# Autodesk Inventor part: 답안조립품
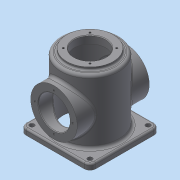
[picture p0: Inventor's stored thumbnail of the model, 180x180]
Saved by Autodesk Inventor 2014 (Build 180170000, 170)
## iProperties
Created: 2015-10
Part Number: 답안조립품
Material: 일반
Document SubType Name: Modeling
Designer: net
Density: 1 g/cm^3
Appearance: 기본값
Author: net
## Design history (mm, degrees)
sketch "스케치1"
  geometry: L1 (60, -60)-(-60, -60); L2 (-60, -60)-(-60, 60); L3 (-60, 60)-(60, 60); L4 (60, 60)-(60, -60); L5 (60, 0)-(-60, 0); C1 r 4 at (50, -50); C2 r 4 at (-50, -50); C3 r 4 at (50, 50); C4 r 4 at (-50, 50); 2 further points
  constraints: 10 end point, 4 centre point, 3 midpoint, 2 horizontal alignment, 2 parallel, 2 perpendicular, 2 symmetric about line, 1 equal radius, 1 horizontal, 1 vertical alignment, 2 other
  dimensions: "d0" = 120 distance of L1.start L1.end; "d1" = 120 distance of L1.end L2.end; "d2" = 8 diameter of C1; "d3" = 50 horizontal distance of C1.centre point (0, 0); "d4" = 50 horizontal distance of point (0, 0) C1.centre; "d5" = 100 distance of C2.centre C1.centre
extrude "돌출1" new body sketch "스케치1" distance "d6" = 10; taper "d7" = 0 deg
fillet "모깎기1" dims "d8" = 10
node "작업 평면2"
sketch "스케치2"
  geometry: C1 r 50 at (0, 0); C2 r 40 at (0, 0); 1 further point
  constraints: 2 centre point, 2 coincident
  dimensions: "d10" = 100 diameter of C1; "d13" = 80 diameter of C2
extrude "돌출2" join sketch "스케치2" stored distance "d11" = 10; taper "d12" = 0 deg
extrude "돌출3" join sketch "스케치2" distance "d14" = 5; taper "d15" = 0 deg
hole "구멍1" diameter "d18" = 54; stored, may be unused: countersink angle "d22" = 90 deg, drill point angle "d24" = 0 deg; dims "d16" = 10, "d17" = 10, "d19" = 6, "d20" = 4, "d21" = 2, "d23" = 13
hole "구멍2" diameter "d27" = 90; stored, may be unused: countersink angle "d31" = 90 deg, drill point angle "d33" = 0 deg; dims "d25" = 10, "d26" = 10, "d28" = 6, "d29" = 4, "d30" = 2, "d32" = 112
node "작업 평면3"
sketch "스케치3"
  geometry: L1 (40, 125)-(-40, 125) reference; L2 (50, 0)-(-50, 0) reference; L3 (50, 120)-(50, 10) reference; L4 (-50, 120)-(-50, 10) reference; L5 (0, 60)-(-32.5, 60); L6 (0, 60)-(32.5, 60); C1 r 40 at (0, 60); A1 r 32.5 centre (0, 60) between (0, 92.5) and (0, 27.5); 3 further points
  constraints: 4 end point, 4 point on circle, 2 centre point, 2 midpoint, 1 coincident, 1 collinear, 1 perpendicular, 1 vertical alignment
  dimensions: "d35" = 80 diameter of C1; "d38" = 65 diameter of A1; "d82" = 60 distance from line of L2 C1.centre
extrude "돌출4" join sketch "스케치3" stored distance "d36" = 5; taper "d37" = 0 deg
hole "구멍8" sketch "스케치3" diameter "d103" = 3.242; stored, may be unused: countersink angle "d107" = 90 deg, drill point angle "d109" = 118 deg; dims "d104" = 8, "d105" = 4, "d106" = 2, "d108" = 10
hole "구멍4" diameter "d48" = 54; stored, may be unused: countersink angle "d52" = 90 deg, drill point angle "d54" = 0 deg; dims "d49" = 8, "d50" = 4, "d51" = 2, "d53" = 10, "d55" = 10, "d56" = 10
sketch "스케치4"
  geometry: L1 (0, 32.5)-(0, 0); L2 (0, 0)-(22.981, 22.981); L3 (0, 0)-(-22.981, 22.981); L4 (2.311, 0)-(32.5, 0); C1 r 40 at (0, 0) reference; A1 r 32.5 centre (0, 0) between (0, 32.5) and (22.981, 22.981); 1 further point
  constraints: 8 end point, 4 point on circle, 2 coincident, 1 centre point, 1 perpendicular, 1 vertical
  dimensions: "d57" = 65 diameter of A1; "d58" = 90 deg angle of L2 L3; "d60" = 45 deg angle of L4 L2
hole "구멍6" sketch "스케치4" at (22.981, 22.981) diameter "d70" = 3.242; stored, may be unused: countersink angle "d74" = 90 deg, drill point angle "d76" = 118 deg; dims "d71" = 8, "d72" = 4, "d73" = 2, "d75" = 10
node "작업 평면4"
sketch "스케치5"
  geometry: L1 (0, 50)-(0, -50) reference; L2 (-125, 40)-(-125, -40) reference; L3 (-100, 62)-(-20, 62) reference; 3 further points
  constraints: 1 horizontal alignment, 1 midpoint, 1 other
  dimensions: "d84" = 70 distance from line of L1 point (-70, 0)
feature "엠보싱1" sketch "스케치5" dims "d0" = 120, "d1" = 120, "d2" = 8, "d3" = 50, "d4" = 50, "d5" = 100, "d85" = 0.5, "d86" = 0
fillet "모깎기2" dims "d87" = 3, "d95" = 5
fillet "모깎기3" dims "d88" = 3
chamfer "모따기1" distance "d89" = 1; stored, may be unused: second distance "d90" = 2, angle "d91" = 45 deg
chamfer "모따기2" distance "d92" = 3; stored, may be unused: second distance "d93" = 2, angle "d94" = 45 deg
node "솔리드1"
mirror "대칭2"
pattern_circular "원형 패턴1" dims angle "d78" = 360 deg
other parameters: "d34" = 62, "d80" = -55
